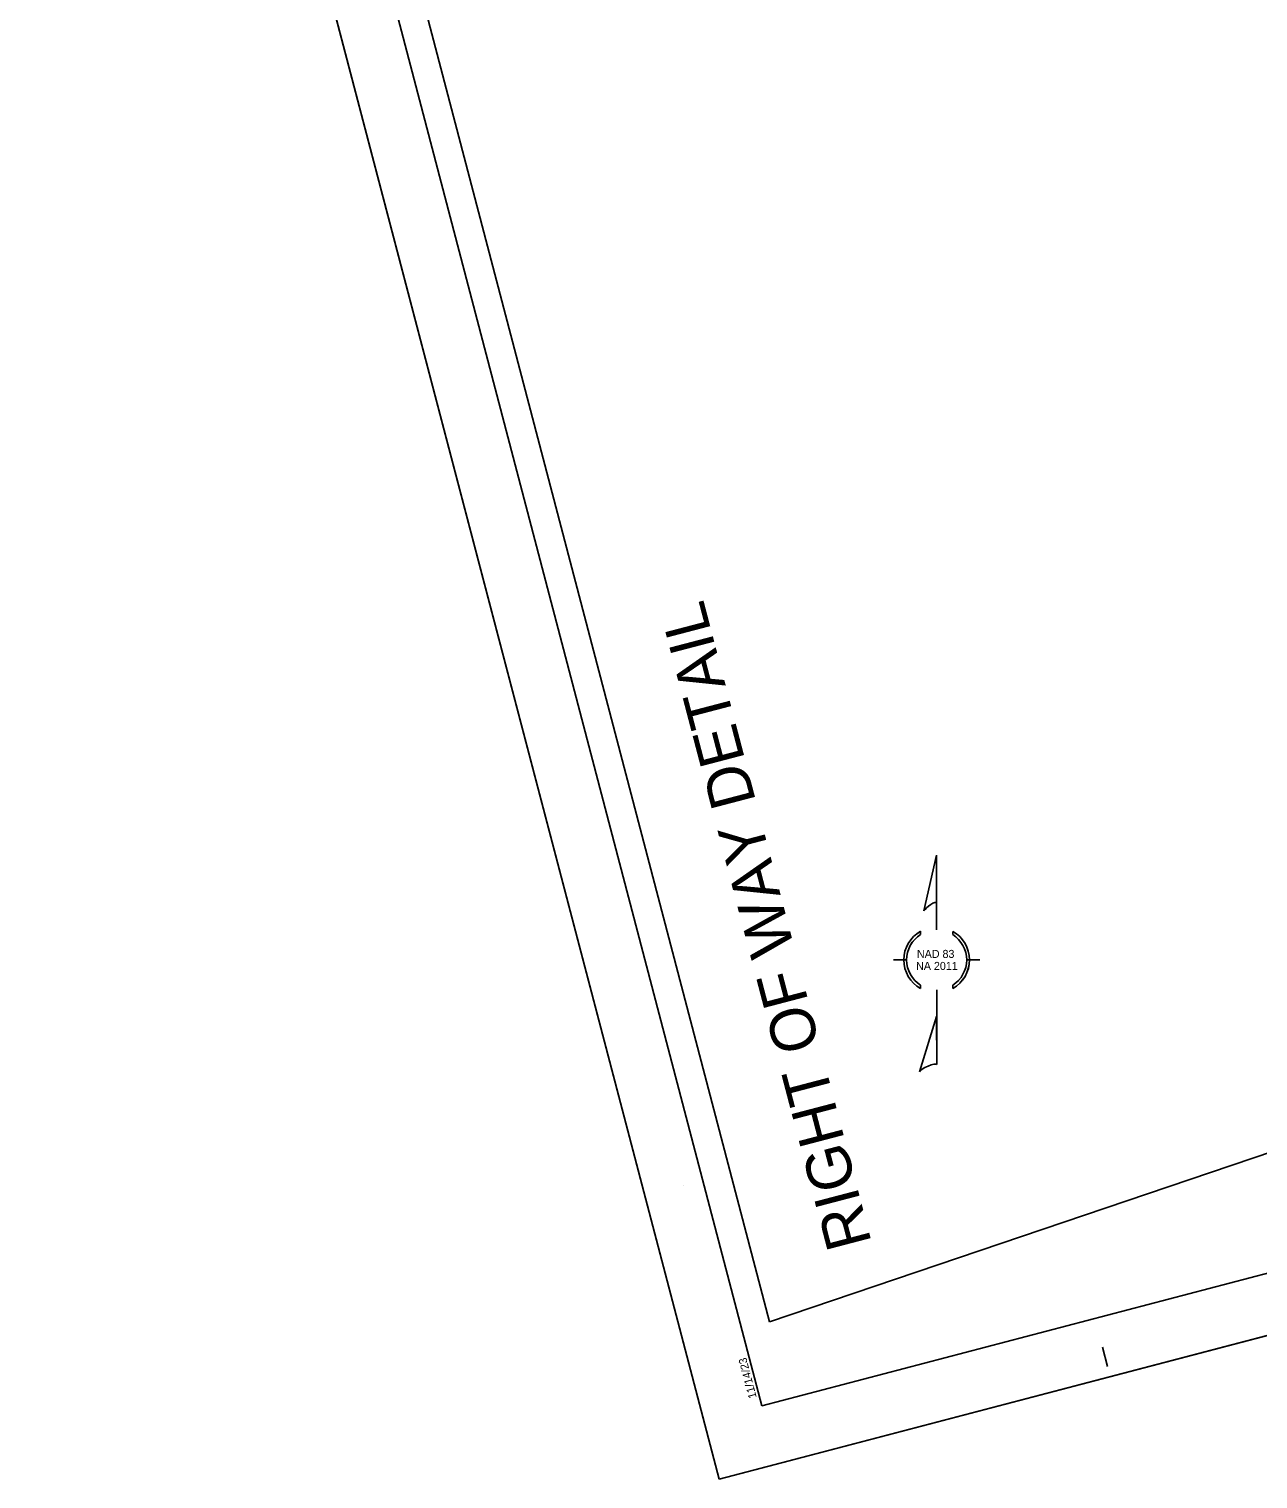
# Model space of a CAD drawing. Extents: x 1366396 to 1367943, y 879298 to 881235.
# Drawn here: x 1366408 to 1367175, y 879298 to 880204 of the extents above; entities that cross this region are included whole.
import ezdxf

# ---------------------------------------------------------------- set-up
doc = ezdxf.new("R2010")
doc.units = 0
for name, color, linetype in [('Draft_RDY_Construction_Class_Element', 7, 'Continuous'), ('Old_Level_1', 7, 'Continuous'), ('P_RDY_Dimension_Text', 7, 'Continuous'), ('P_RDY_Easement_Permanent_Utility', 7, 'Continuous'), ('Prop GRAU CAT1 Cell', 7, 'Continuous'), ('Prop Horizontal Alignment Tick Small', 7, 'Continuous'), ('Prop Superelevation Label', 7, 'Continuous')]:
    doc.layers.add(name, color=color, linetype=linetype)

msp = doc.modelspace()

# ---------------------------------------------------------------- linework, layer by layer
at = {"layer": 'Draft_RDY_Construction_Class_Element'}
msp.add_lwpolyline([(1366838.49, 879297.82), (1366407.53, 880942.29), (1367471.6, 881221.14), (1367902.56, 879576.68)], close=True, dxfattribs=at)
at = {"layer": 'Old_Level_1'}
for p, q in [((1366838.49, 879297.82), (1366407.53, 880942.29)), ((1367902.56, 879576.68), (1366838.49, 879297.82))]:
    msp.add_line(p, q, dxfattribs=at)
at = {"layer": 'P_RDY_Dimension_Text'}
for p, q in [((1366966.46, 879652.71), (1366974.33, 879687.48)), ((1366974.36, 879687.48), (1366974.33, 879687.48)), ((1366974.36, 879687.48), (1366974.33, 879687.48)), ((1366974.36, 879687.48), (1366974.37, 879657.01)), ((1366974.38, 879640.88), (1366974.36, 879687.48)), ((1366974.37, 879657.01), (1366974.37, 879657.87)), ((1366974.37, 879657.87), (1366974.39, 879657.87)), ((1366964.3, 879640), (1366964.3, 879639.98)), ((1366964.3, 879639.98), (1366964.31, 879637.94)), ((1366984.48, 879637.93), (1366984.48, 879639.98)), ((1366947.39, 879622.12), (1366955.64, 879622.13)), ((1366955.64, 879622.13), (1366953.89, 879622.12)), ((1366953.89, 879622.12), (1366955.64, 879622.13)), ((1366993.14, 879622.14), (1367001.39, 879622.14)), ((1366993.14, 879622.14), (1366994.89, 879622.14)), ((1366994.89, 879622.14), (1366993.14, 879622.14)), ((1366964.32, 879606.32), (1366964.32, 879604.27)), ((1366974.41, 879556.78), (1366974.4, 879603.38)), ((1366984.5, 879604.3), (1366984.5, 879606.34)), ((1366984.5, 879604.28), (1366984.5, 879604.3)), ((1366974.38, 879586.78), (1366963.64, 879552.31)), ((1366974.42, 879556.79), (1366974.38, 879586.78))]:
    msp.add_line(p, q, dxfattribs=at)
for radius, start, end in [(20.5, 119.45812, 240.5898), (18.75, 122.52712, 237.52079), (20.5, 299.54438, 60.50354), (20.5, 0.02396, 60.50354), (18.75, 302.62453, 57.42338), (18.75, 0.02396, 57.42338), (20.5, 180.02396, 240.5898), (18.75, 180.02396, 237.52079)]:
    msp.add_arc((1366974.39, 879622.13), radius, start, end, dxfattribs=at)
for centre, major_axis, ratio, start_param, end_param in [((1366970.36, 879654.87), (3.99, 3.06), 0.261723, 6.225794, 8.917625), ((1366974.39, 879622.13), (-0.01, 20.53), 0.998737, 0.514018, 1.570796), ((1366974.39, 879622.13), (-0.01, 18.77), 0.998737, 0.567287, 1.570796), ((1366974.39, 879622.13), (-0.01, 18.77), 0.998737, 3.71058, 4.712389), ((1366974.39, 879622.13), (-0.01, 20.53), 0.998737, 3.657116, 4.712389), ((1366969.03, 879554.36), (5.38, 2.43), 0.225493, 6.280036, 9.220301)]:
    msp.add_ellipse(centre, major_axis=major_axis, ratio=ratio, start_param=start_param, end_param=end_param, dxfattribs=at)
at = {"layer": 'P_RDY_Easement_Permanent_Utility'}
msp.add_line((1366816.27, 879481.17), (1366816.27, 879481.17), dxfattribs=at)
at = {"layer": 'Prop GRAU CAT1 Cell'}
msp.add_lwpolyline([(1366869.99, 879396.08), (1366503.15, 880795.86), (1367465.82, 881048.15), (1367814.91, 879716.05)], close=True, dxfattribs=at)
at = {"layer": 'Prop Superelevation Label'}
for p, q in [((1366453.31, 880915.52), (1366865.26, 879343.61)), ((1367856.78, 879603.43), (1366865.26, 879343.61)), ((1367081.09, 879368.13), (1367077.89, 879380.23)), ((1366850.38, 879370.68), (1366850.38, 879370.68))]:
    msp.add_line(p, q, dxfattribs=at)

# ---------------------------------------------------------------- texts
at = {"layer": 'P_RDY_Dimension_Text'}
for s, p in [('NAD 83', (1366962.08, 879623.38)), ('NA 2011', (1366961.54, 879615.88))]:
    msp.add_text(s, height=5, rotation=0.02396, dxfattribs=at).set_placement(p)
at = {"layer": 'Prop Horizontal Alignment Tick Small'}
msp.add_text('RIGHT OF WAY DETAIL', height=28, rotation=104.68512, dxfattribs=at).set_placement((1366933.94, 879445.35))
at = {"layer": 'Prop Superelevation Label'}
msp.add_text('11/14/23', height=5, rotation=104.68512, dxfattribs=at).set_placement((1366862.02, 879348.84))

doc.saveas('drawing.dxf')
